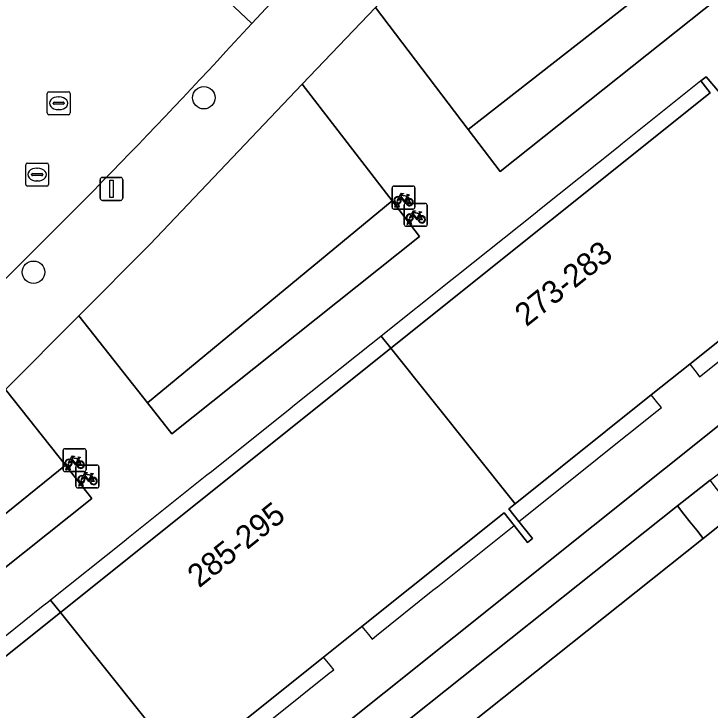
# Model space of a CAD drawing. Extents: x 159039 to 160102, y 381214 to 382524.
# Drawn here: x 159523.2 to 159553.55, y 381664.14 to 381694.48 of the extents above; entities that cross this region are included whole.
import ezdxf

# ---------------------------------------------------------------- set-up
doc = ezdxf.new("R2010")
doc.units = 0
for name, color, linetype in [('IMGEO_Boom', 7, 'Continuous'), ('IMGEO_Erf', 7, 'Continuous'), ('IMGEO_Fietsenrek', 7, 'Continuous'), ('IMGEO_Groenvoorziening', 7, 'Continuous'), ('IMGEO_Haag', 7, 'Continuous'), ('IMGEO_Lichtmast', 7, 'Continuous'), ('IMGEO_Pand', 7, 'Continuous'), ('IMGEO_Pand_nummerreeks', 7, 'Continuous'), ('IMGEO_Pand_overbouw', 7, 'Continuous'), ('IMGEO_Parkeervlak_open', 7, 'Continuous'), ('IMGEO_Rijbaan_lokaal_open', 7, 'Continuous'), ('IMGEO_Rioolput', 7, 'Continuous'), ('IMGEO_Voetpad_gesloten', 7, 'Continuous'), ('IMGEO_Voetpad_open', 7, 'Continuous')]:
    doc.layers.add(name, color=color, linetype=linetype)

msp = doc.modelspace()

# ---------------------------------------------------------------- linework, layer by layer
at = {"layer": 'IMGEO_Boom'}
for centre in [(159531.476, 381690.832), (159524.052, 381683.223)]:
    msp.add_circle(centre, 0.489, dxfattribs=at)
at = {"layer": 'IMGEO_Erf'}
for points in [[(159558.941, 381684.231), (159552.662, 381679.211), (159550.989, 381677.874), (159545.05, 381673.126), (159544.771, 381672.902), (159545.21, 381672.353), (159545.804, 381671.609), (159545.597, 381671.439), (159545.004, 381672.187), (159544.572, 381672.732), (159538.373, 381667.778), (159536.701, 381666.442), (159530.643, 381661.602)], [(159517.986, 381647.841), (159560.674, 381681.936), (159563.337, 381681.842), (159568.876, 381676.789), (159590.803, 381656.219)]]:
    msp.add_lwpolyline(points, dxfattribs=at)
at = {"layer": 'IMGEO_Fietsenrek'}
for p, q in [((159539.758, 381686.977), (159540.599, 381686.977)), ((159540.599, 381686.977), (159539.758, 381686.977)), ((159539.683, 381686.052), (159539.683, 381686.893)), ((159539.683, 381686.893), (159539.683, 381686.052)), ((159540.683, 381686.902), (159540.683, 381686.061)), ((159540.683, 381686.061), (159540.683, 381686.902)), ((159540.37, 381686.526), (159540.406, 381686.431)), ((159539.81, 381686.061), (159539.849, 381686.221)), ((159539.844, 381686.061), (159539.81, 381686.061)), ((159539.879, 381686.209), (159539.844, 381686.061)), ((159539.921, 381686.233), (159539.92, 381686.237)), ((159539.962, 381686.061), (159539.928, 381686.203)), ((159539.952, 381686.244), (159539.953, 381686.237)), ((159539.96, 381686.207), (159539.995, 381686.061)), ((159539.995, 381686.061), (159539.962, 381686.061)), ((159540.214, 381685.299), (159540.214, 381686.14)), ((159540.214, 381686.14), (159540.214, 381685.299)), ((159540.289, 381686.224), (159541.13, 381686.224)), ((159541.13, 381686.224), (159540.289, 381686.224)), ((159541.214, 381686.149), (159541.214, 381685.308)), ((159541.214, 381685.308), (159541.214, 381686.149)), ((159540.608, 381685.977), (159539.767, 381685.977)), ((159539.767, 381685.977), (159540.608, 381685.977)), ((159540.901, 381685.773), (159540.937, 381685.678)), ((159540.341, 381685.308), (159540.38, 381685.468)), ((159540.41, 381685.456), (159540.375, 381685.308)), ((159540.452, 381685.48), (159540.451, 381685.484)), ((159540.493, 381685.308), (159540.459, 381685.45)), ((159540.483, 381685.491), (159540.484, 381685.484)), ((159540.491, 381685.454), (159540.526, 381685.308)), ((159541.139, 381685.224), (159540.298, 381685.224)), ((159540.298, 381685.224), (159541.139, 381685.224)), ((159540.375, 381685.308), (159540.341, 381685.308)), ((159540.526, 381685.308), (159540.493, 381685.308)), ((159525.34, 381674.605), (159525.34, 381675.446)), ((159525.34, 381675.446), (159525.34, 381674.605)), ((159525.415, 381675.53), (159526.256, 381675.53)), ((159526.256, 381675.53), (159525.415, 381675.53)), ((159526.34, 381675.455), (159526.34, 381674.614)), ((159526.34, 381674.614), (159526.34, 381675.455)), ((159526.027, 381675.079), (159526.063, 381674.984)), ((159525.467, 381674.614), (159525.506, 381674.774)), ((159525.578, 381674.786), (159525.577, 381674.79)), ((159525.609, 381674.797), (159525.61, 381674.79)), ((159525.977, 381674.818), (159526.818, 381674.818)), ((159526.818, 381674.818), (159525.977, 381674.818)), ((159526.265, 381674.53), (159525.424, 381674.53)), ((159525.424, 381674.53), (159526.265, 381674.53)), ((159525.501, 381674.614), (159525.467, 381674.614)), ((159525.536, 381674.762), (159525.501, 381674.614)), ((159525.619, 381674.614), (159525.585, 381674.756)), ((159525.617, 381674.76), (159525.652, 381674.614)), ((159525.652, 381674.614), (159525.619, 381674.614)), ((159525.902, 381673.893), (159525.902, 381674.734)), ((159525.902, 381674.734), (159525.902, 381673.893)), ((159526.902, 381674.743), (159526.902, 381673.902)), ((159526.902, 381673.902), (159526.902, 381674.743)), ((159526.589, 381674.367), (159526.625, 381674.272)), ((159526.029, 381673.902), (159526.068, 381674.062)), ((159526.063, 381673.902), (159526.029, 381673.902)), ((159526.098, 381674.05), (159526.063, 381673.902)), ((159526.14, 381674.074), (159526.139, 381674.078)), ((159526.181, 381673.902), (159526.147, 381674.044)), ((159526.171, 381674.085), (159526.172, 381674.078)), ((159526.179, 381674.048), (159526.214, 381673.902)), ((159526.214, 381673.902), (159526.181, 381673.902)), ((159526.827, 381673.818), (159525.986, 381673.818)), ((159525.986, 381673.818), (159526.827, 381673.818))]:
    msp.add_line(p, q, dxfattribs=at)
for points in [[(159539.996, 381686.503), (159540.091, 381686.667), (159540.177, 381686.653), (159540.179, 381686.644), (159540.123, 381686.633), (159540.096, 381686.588), (159540.352, 381686.547)], [(159540.352, 381686.547), (159540.377, 381686.596), (159540.371, 381686.6), (159540.348, 381686.604), (159540.336, 381686.611), (159540.335, 381686.614), (159540.337, 381686.619), (159540.432, 381686.604), (159540.434, 381686.594), (159540.424, 381686.581), (159540.412, 381686.575), (159540.398, 381686.581), (159540.37, 381686.526)], [(159540.017, 381686.451), (159539.965, 381686.361), (159539.925, 381686.336), (159539.926, 381686.383), (159539.981, 381686.477)], [(159540.292, 381686.259), (159540.242, 381686.259), (159540.051, 381686.51), (159540.032, 381686.478)], [(159540.339, 381686.522), (159540.082, 381686.563), (159540.065, 381686.534), (159540.232, 381686.314), (159540.339, 381686.522)], [(159540.387, 381686.424), (159540.357, 381686.501), (159540.248, 381686.283), (159540.291, 381686.283)], [(159540.321, 381686.283), (159540.441, 381686.282), (159540.397, 381686.396)], [(159540.417, 381686.403), (159540.472, 381686.258), (159540.322, 381686.258)], [(159540.548, 381685.698), (159540.496, 381685.608), (159540.456, 381685.583), (159540.457, 381685.63), (159540.512, 381685.724)], [(159540.527, 381685.75), (159540.622, 381685.914), (159540.708, 381685.9), (159540.71, 381685.891), (159540.654, 381685.88), (159540.627, 381685.835), (159540.883, 381685.794)], [(159540.823, 381685.506), (159540.773, 381685.506), (159540.582, 381685.757), (159540.563, 381685.725)], [(159540.87, 381685.769), (159540.613, 381685.81), (159540.596, 381685.781), (159540.763, 381685.561), (159540.87, 381685.769)], [(159540.918, 381685.671), (159540.888, 381685.748), (159540.779, 381685.53), (159540.822, 381685.53)], [(159540.883, 381685.794), (159540.908, 381685.843), (159540.902, 381685.847), (159540.879, 381685.851), (159540.867, 381685.858), (159540.866, 381685.861), (159540.868, 381685.866), (159540.963, 381685.851), (159540.965, 381685.841), (159540.955, 381685.828), (159540.943, 381685.822), (159540.929, 381685.828), (159540.901, 381685.773)], [(159540.852, 381685.53), (159540.972, 381685.529), (159540.928, 381685.643)], [(159540.948, 381685.65), (159541.003, 381685.505), (159540.853, 381685.505)], [(159525.653, 381675.056), (159525.748, 381675.22), (159525.834, 381675.206), (159525.836, 381675.197), (159525.78, 381675.186), (159525.753, 381675.141), (159526.009, 381675.1)], [(159525.996, 381675.075), (159525.739, 381675.116), (159525.722, 381675.087), (159525.889, 381674.867), (159525.996, 381675.075)], [(159526.009, 381675.1), (159526.034, 381675.149), (159526.028, 381675.153), (159526.005, 381675.157), (159525.993, 381675.164), (159525.992, 381675.167), (159525.994, 381675.172), (159526.089, 381675.157), (159526.091, 381675.147), (159526.081, 381675.134), (159526.069, 381675.128), (159526.055, 381675.134), (159526.027, 381675.079)], [(159525.674, 381675.004), (159525.622, 381674.914), (159525.582, 381674.889), (159525.583, 381674.936), (159525.638, 381675.03)], [(159525.949, 381674.812), (159525.899, 381674.812), (159525.708, 381675.063), (159525.689, 381675.031)], [(159526.044, 381674.977), (159526.014, 381675.054), (159525.905, 381674.836), (159525.948, 381674.836)], [(159525.978, 381674.836), (159526.098, 381674.835), (159526.054, 381674.949)], [(159526.074, 381674.956), (159526.129, 381674.811), (159525.979, 381674.811)], [(159526.215, 381674.344), (159526.31, 381674.508), (159526.396, 381674.494), (159526.398, 381674.485), (159526.342, 381674.474), (159526.315, 381674.429), (159526.571, 381674.388)], [(159526.236, 381674.292), (159526.184, 381674.202), (159526.144, 381674.177), (159526.145, 381674.224), (159526.2, 381674.318)], [(159526.511, 381674.1), (159526.461, 381674.1), (159526.27, 381674.351), (159526.251, 381674.319)], [(159526.558, 381674.363), (159526.301, 381674.404), (159526.284, 381674.375), (159526.451, 381674.155), (159526.558, 381674.363)], [(159526.606, 381674.265), (159526.576, 381674.342), (159526.467, 381674.124), (159526.51, 381674.124)], [(159526.54, 381674.124), (159526.66, 381674.123), (159526.616, 381674.237)], [(159526.636, 381674.244), (159526.691, 381674.099), (159526.541, 381674.099)], [(159526.571, 381674.388), (159526.596, 381674.437), (159526.59, 381674.441), (159526.567, 381674.445), (159526.555, 381674.452), (159526.554, 381674.455), (159526.556, 381674.46), (159526.651, 381674.445), (159526.653, 381674.435), (159526.643, 381674.422), (159526.631, 381674.416), (159526.617, 381674.422), (159526.589, 381674.367)]]:
    msp.add_lwpolyline(points, dxfattribs=at)
for centre, radius, start, end in [((159539.761, 381686.899), 0.0779, 92.4484, 184.2845), ((159539.761, 381686.899), 0.0779, 92.4484, 184.2845), ((159540.605, 381686.899), 0.0779, 2.4484, 94.2845), ((159540.605, 381686.899), 0.0779, 2.4484, 94.2845), ((159539.923, 381686.362), 0.159, 62.6766, 242.1369), ((159539.923, 381686.362), 0.129, 63.3192, 238.903), ((159539.923, 381686.362), 0.129, 283.6043, 43.4302), ((159539.923, 381686.362), 0.159, 283.5766, 46.6042), ((159540.45, 381686.278), 0.159, 113.3408, 178.3217), ((159540.45, 381686.278), 0.159, 187.0065, 105.7708), ((159540.45, 381686.278), 0.129, 113.923, 177.9556), ((159540.45, 381686.278), 0.129, 188.6715, 104.5883), ((159539.761, 381686.055), 0.0779, 182.4484, 274.2845), ((159539.761, 381686.055), 0.0779, 182.4484, 274.2845), ((159539.903, 381686.233), 0.0499, 12.8025, 158.6934), ((159539.923, 381686.362), 0.159, 253.9967, 271.7867), ((159539.903, 381686.233), 0.0174, 12.8025, 163.4502), ((159539.923, 381686.362), 0.129, 253.415, 269.0204), ((159540.292, 381686.146), 0.0779, 92.4484, 184.2845), ((159540.292, 381686.146), 0.0779, 92.4484, 184.2845), ((159540.605, 381686.055), 0.0779, 272.4484, 4.2845), ((159540.605, 381686.055), 0.0779, 272.4484, 4.2845), ((159541.136, 381686.146), 0.0779, 2.4484, 94.2845), ((159541.136, 381686.146), 0.0779, 2.4484, 94.2845), ((159540.454, 381685.609), 0.159, 62.6766, 242.1369), ((159540.454, 381685.609), 0.129, 63.3192, 238.903), ((159540.454, 381685.609), 0.129, 283.6043, 43.4302), ((159540.454, 381685.609), 0.159, 283.5766, 46.6042), ((159540.434, 381685.48), 0.0499, 12.8025, 158.6934), ((159540.454, 381685.609), 0.159, 253.9967, 271.7867), ((159540.434, 381685.48), 0.0174, 12.8025, 163.4502), ((159540.454, 381685.609), 0.129, 253.415, 269.0204), ((159540.981, 381685.525), 0.159, 113.3408, 178.3217), ((159540.981, 381685.525), 0.159, 187.0065, 105.7708), ((159540.981, 381685.525), 0.129, 113.923, 177.9556), ((159540.981, 381685.525), 0.129, 188.6715, 104.5883), ((159540.292, 381685.302), 0.0779, 182.4484, 274.2845), ((159540.292, 381685.302), 0.0779, 182.4484, 274.2845), ((159541.136, 381685.302), 0.0779, 272.4484, 4.2845), ((159541.136, 381685.302), 0.0779, 272.4484, 4.2845), ((159525.418, 381675.452), 0.0779, 92.4484, 184.2845), ((159525.418, 381675.452), 0.0779, 92.4484, 184.2845), ((159526.262, 381675.452), 0.0779, 2.4484, 94.2845), ((159526.262, 381675.452), 0.0779, 2.4484, 94.2845), ((159525.58, 381674.915), 0.159, 62.6766, 242.1369), ((159525.58, 381674.915), 0.129, 63.3192, 238.903), ((159525.56, 381674.786), 0.0499, 12.8025, 158.6934), ((159525.56, 381674.786), 0.0174, 12.8025, 163.4502), ((159525.58, 381674.915), 0.129, 253.415, 269.0204), ((159525.58, 381674.915), 0.129, 283.6043, 43.4302), ((159525.58, 381674.915), 0.159, 283.5766, 46.6042), ((159525.98, 381674.74), 0.0779, 92.4484, 184.2845), ((159525.98, 381674.74), 0.0779, 92.4484, 184.2845), ((159526.107, 381674.831), 0.159, 113.3408, 178.3217), ((159526.107, 381674.831), 0.159, 187.0065, 105.7708), ((159526.107, 381674.831), 0.129, 113.923, 177.9556), ((159526.107, 381674.831), 0.129, 188.6715, 104.5883), ((159526.824, 381674.74), 0.0779, 2.4484, 94.2845), ((159526.824, 381674.74), 0.0779, 2.4484, 94.2845), ((159525.418, 381674.608), 0.0779, 182.4484, 274.2845), ((159525.418, 381674.608), 0.0779, 182.4484, 274.2845), ((159525.58, 381674.915), 0.159, 253.9967, 271.7867), ((159526.262, 381674.608), 0.0779, 272.4484, 4.2845), ((159526.262, 381674.608), 0.0779, 272.4484, 4.2845), ((159526.142, 381674.203), 0.159, 62.6766, 242.1369), ((159526.142, 381674.203), 0.129, 63.3192, 238.903), ((159526.142, 381674.203), 0.129, 283.6043, 43.4302), ((159526.142, 381674.203), 0.159, 283.5766, 46.6042), ((159526.669, 381674.119), 0.159, 113.3408, 178.3217), ((159526.669, 381674.119), 0.159, 187.0065, 105.7708), ((159526.669, 381674.119), 0.129, 113.923, 177.9556), ((159526.669, 381674.119), 0.129, 188.6715, 104.5883), ((159525.98, 381673.896), 0.0779, 182.4484, 274.2845), ((159525.98, 381673.896), 0.0779, 182.4484, 274.2845), ((159526.122, 381674.074), 0.0499, 12.8025, 158.6934), ((159526.142, 381674.203), 0.159, 253.9967, 271.7867), ((159526.122, 381674.074), 0.0174, 12.8025, 163.4502), ((159526.142, 381674.203), 0.129, 253.415, 269.0204), ((159526.824, 381673.896), 0.0779, 272.4484, 4.2845), ((159526.824, 381673.896), 0.0779, 272.4484, 4.2845)]:
    msp.add_arc(centre, radius, start, end, dxfattribs=at)
at = {"layer": 'IMGEO_Groenvoorziening'}
for points in [[(159552.118, 381708.936), (159538.96, 381694.765), (159543.002, 381689.45), (159559.385, 381702.243)], [(159544.393, 381687.62), (159560.959, 381700.793), (159559.385, 381702.243), (159543.002, 381689.45)], [(159526.033, 381681.326), (159529.018, 381677.537), (159539.688, 381686.33), (159535.768, 381691.423), (159529.122, 381684.438)], [(159530.088, 381676.179), (159540.878, 381684.784), (159539.688, 381686.33), (159529.018, 381677.537)], [(159512.874, 381668.486), (159514.696, 381666.122), (159525.44, 381674.816), (159522.833, 381678.114)], [(159515.763, 381664.736), (159526.592, 381673.359), (159525.44, 381674.816), (159514.696, 381666.122)], [(159553.246, 381671.62), (159552.968, 381671.974), (159552.69, 381672.328), (159552.412, 381672.682), (159552.129, 381673.041), (159539.094, 381662.668), (159539.379, 381662.302), (159539.656, 381661.947), (159539.933, 381661.592), (159540.21, 381661.238)]]:
    msp.add_lwpolyline(points, close=True, dxfattribs=at)
msp.add_lwpolyline([(159559.955, 381676.816), (159554.67, 381672.743), (159553.246, 381671.62), (159540.21, 381661.238), (159538.785, 381660.093), (159526.133, 381649.947), (159524.729, 381648.803), (159520.146, 381645.173), (159518.283, 381643.698), (159520.549, 381641.574)], dxfattribs=at)
at = {"layer": 'IMGEO_Haag'}
for points in [[(159530.088, 381676.179), (159540.878, 381684.784), (159539.688, 381686.33), (159529.018, 381677.537)], [(159515.763, 381664.736), (159526.592, 381673.359), (159525.44, 381674.816), (159514.696, 381666.122)], [(159553.246, 381671.62), (159552.968, 381671.974), (159552.69, 381672.328), (159552.412, 381672.682), (159552.129, 381673.041), (159539.094, 381662.668), (159539.379, 381662.302), (159539.656, 381661.947), (159539.933, 381661.592), (159540.21, 381661.238)]]:
    msp.add_lwpolyline(points, close=True, dxfattribs=at)
at = {"layer": 'IMGEO_Lichtmast'}
for p, q in [((159526.953, 381686.457), (159526.953, 381687.257)), ((159526.953, 381687.257), (159526.953, 381686.457)), ((159527.053, 381687.357), (159527.843, 381687.357)), ((159527.843, 381687.357), (159527.053, 381687.357)), ((159527.943, 381687.257), (159527.943, 381686.457)), ((159527.943, 381686.457), (159527.943, 381687.257)), ((159527.843, 381686.357), (159527.053, 381686.357)), ((159527.053, 381686.357), (159527.843, 381686.357))]:
    msp.add_line(p, q, dxfattribs=at)
msp.add_lwpolyline([(159527.373, 381687.232), (159527.523, 381687.232), (159527.523, 381686.482), (159527.373, 381686.482), (159527.373, 381687.232)], dxfattribs=at)
for centre, start, end in [((159527.053, 381687.257), 90, 180), ((159527.053, 381687.257), 90, 180), ((159527.843, 381687.257), 0, 90), ((159527.843, 381687.257), 360, 90), ((159527.053, 381686.457), 180, 270), ((159527.053, 381686.457), 180, 270), ((159527.843, 381686.457), 270, 0), ((159527.843, 381686.457), 270, 0)]:
    msp.add_arc(centre, 0.1, start, end, dxfattribs=at)
at = {"layer": 'IMGEO_Pand'}
for points in [[(159560.022, 381684.192), (159554.358, 381690.875), (159554.21, 381690.76), (159553.382, 381691.743), (159553.148, 381691.563), (159553.55, 381691.042), (159539.633, 381679.917), (159545.05, 381673.126), (159550.989, 381677.874), (159552.662, 381679.211), (159558.941, 381684.231), (159559.37, 381683.693), (159559.846, 381683.094), (159559.969, 381683.194), (159560.081, 381683.281), (159559.612, 381683.878)], [(159525.223, 381668.397), (159530.643, 381661.602), (159536.701, 381666.442), (159538.373, 381667.778), (159544.572, 381672.732), (159545.004, 381672.187), (159545.597, 381671.439), (159545.804, 381671.609), (159545.21, 381672.353), (159544.771, 381672.902), (159545.05, 381673.126), (159539.633, 381679.917)], [(159525.223, 381668.397), (159510.714, 381656.799), (159510.259, 381657.341), (159510.034, 381657.157), (159516.34, 381649.275), (159516.469, 381649.378), (159516.574, 381649.462), (159516.137, 381650.009), (159522.394, 381655.014), (159524.075, 381656.36), (159530.263, 381661.309), (159530.703, 381660.756), (159531.304, 381660.003), (159531.511, 381660.175), (159530.909, 381660.92), (159530.47, 381661.464), (159530.643, 381661.602)]]:
    msp.add_lwpolyline(points, close=True, dxfattribs=at)
at = {"layer": 'IMGEO_Pand_overbouw'}
for points in [[(159553.148, 381691.563), (159549.727, 381688.831), (159549.539, 381688.681), (159546.112, 381685.945), (159545.918, 381685.79), (159542.502, 381683.063), (159542.305, 381682.906), (159539.216, 381680.44), (159539.633, 381679.917), (159553.55, 381691.042)], [(159559.37, 381683.693), (159558.941, 381684.231), (159552.662, 381679.211), (159552.939, 381678.865), (159553.095, 381678.67), (159553.292, 381678.828), (159555.778, 381680.818), (159555.98, 381680.979)], [(159539.633, 381679.917), (159539.216, 381680.44), (159538.972, 381680.245), (159538.774, 381680.088), (159535.436, 381677.422), (159535.246, 381677.271), (159531.809, 381674.527), (159531.614, 381674.372), (159528.2, 381671.646), (159528.001, 381671.487), (159524.798, 381668.93), (159525.223, 381668.397)], [(159545.05, 381673.126), (159544.771, 381672.902), (159545.21, 381672.353), (159548.537, 381675.014), (159548.717, 381675.158), (159551.234, 381677.172), (159551.427, 381677.326), (159551.271, 381677.521), (159550.989, 381677.874)], [(159538.373, 381667.778), (159538.654, 381667.427), (159538.81, 381667.232), (159539.004, 381667.387), (159541.469, 381669.359), (159541.665, 381669.516), (159545.004, 381672.187), (159544.572, 381672.732)], [(159525.223, 381668.397), (159524.798, 381668.93), (159524.677, 381668.833), (159524.478, 381668.675), (159521.138, 381666.008), (159520.939, 381665.849), (159517.513, 381663.114), (159517.312, 381662.954), (159513.901, 381660.23), (159513.697, 381660.068), (159510.259, 381657.341), (159510.714, 381656.799)], [(159530.643, 381661.602), (159530.47, 381661.464), (159530.909, 381660.92), (159534.256, 381663.592), (159534.448, 381663.745), (159536.948, 381665.741), (159537.139, 381665.894), (159536.983, 381666.089), (159536.701, 381666.442)]]:
    msp.add_lwpolyline(points, close=True, dxfattribs=at)
at = {"layer": 'IMGEO_Parkeervlak_open'}
msp.add_lwpolyline([(159546.267, 381710.129), (159544.91, 381708.807), (159532.297, 381695.293), (159533.57, 381694.071), (159545.425, 381706.782)], dxfattribs=at)
at = {"layer": 'IMGEO_Rijbaan_lokaal_open'}
msp.add_lwpolyline([(159533.57, 381694.071), (159532.297, 381695.293), (159529.21, 381698.27), (159528.664, 381697.665), (159527.907, 381696.872)], dxfattribs=at)
msp.add_arc((159323.736, 381885.879), 284.29, 313.99126, 317.56976, dxfattribs=at)
at = {"layer": 'IMGEO_Rioolput'}
for p, q in [((159524.65, 381690.165), (159524.65, 381691.017)), ((159524.725, 381691.091), (159525.577, 381691.091)), ((159525.138, 381690.871), (159525.163, 381690.871)), ((159525.651, 381691.017), (159525.651, 381690.165)), ((159524.909, 381690.585), (159524.909, 381690.597)), ((159524.952, 381690.634), (159525.35, 381690.634)), ((159525.393, 381690.597), (159525.393, 381690.585)), ((159525.347, 381690.548), (159524.949, 381690.548)), ((159525.161, 381690.311), (159525.136, 381690.311)), ((159525.577, 381690.091), (159524.725, 381690.091)), ((159523.71, 381687.054), (159523.71, 381687.906)), ((159523.785, 381687.98), (159524.637, 381687.98)), ((159524.711, 381687.906), (159524.711, 381687.054)), ((159524.012, 381687.523), (159524.41, 381687.523)), ((159524.198, 381687.76), (159524.223, 381687.76)), ((159523.969, 381687.474), (159523.969, 381687.486)), ((159524.407, 381687.437), (159524.009, 381687.437)), ((159524.453, 381687.486), (159524.453, 381687.474)), ((159524.637, 381686.98), (159523.785, 381686.98)), ((159524.221, 381687.2), (159524.196, 381687.2))]:
    msp.add_line(p, q, dxfattribs=at)
for points in [[(159524.65, 381690.165), (159524.65, 381691.017)], [(159524.725, 381691.091), (159525.577, 381691.091)], [(159525.651, 381691.017), (159525.651, 381690.165)], [(159525.577, 381690.091), (159524.725, 381690.091)], [(159523.71, 381687.054), (159523.71, 381687.906)], [(159523.785, 381687.98), (159524.637, 381687.98)], [(159524.711, 381687.906), (159524.711, 381687.054)], [(159524.637, 381686.98), (159523.785, 381686.98)]]:
    msp.add_lwpolyline(points, dxfattribs=at)
for centre, radius, start, end in [((159524.727, 381691.015), 0.0765, 91.552, 178.448), ((159524.727, 381691.015), 0.0765, 91.552, 178.448), ((159525.575, 381691.015), 0.0765, 1.552, 88.448), ((159525.575, 381691.015), 0.0765, 1.552, 88.448), ((159524.949, 381690.594), 0.0403, 85.8775, 175.7526), ((159524.946, 381690.584), 0.0366, 178.938, 274.7102), ((159525.35, 381690.591), 0.043, 264.8664, 352.4533), ((159525.354, 381690.596), 0.0386, 1.7309, 96.639), ((159524.727, 381690.167), 0.0765, 181.552, 268.448), ((159524.727, 381690.167), 0.0765, 181.552, 268.448), ((159525.575, 381690.167), 0.0765, 271.552, 358.448), ((159525.575, 381690.167), 0.0765, 271.552, 358.448), ((159523.787, 381687.904), 0.0765, 91.552, 178.448), ((159523.787, 381687.904), 0.0765, 91.552, 178.448), ((159524.635, 381687.904), 0.0765, 1.552, 88.448), ((159524.635, 381687.904), 0.0765, 1.552, 88.448), ((159524.009, 381687.483), 0.0403, 85.8775, 175.7526), ((159524.414, 381687.485), 0.0386, 1.7309, 96.639), ((159524.006, 381687.473), 0.0366, 178.938, 274.7102), ((159524.41, 381687.48), 0.043, 264.8664, 352.4533), ((159523.787, 381687.056), 0.0765, 181.552, 268.448), ((159523.787, 381687.056), 0.0765, 181.552, 268.448), ((159524.635, 381687.056), 0.0765, 271.552, 358.448), ((159524.635, 381687.056), 0.0765, 271.552, 358.448)]:
    msp.add_arc(centre, radius, start, end, dxfattribs=at)
for centre, major_axis, ratio, start_param, end_param in [((159525.137, 381690.591), (-0.387, 0.002), 0.722429, 4.712389, 7.853982), ((159525.162, 381690.591), (-0.39, 0.002), 0.717154, 1.570796, 4.712389), ((159524.197, 381687.48), (-0.387, 0.002), 0.722429, 4.712389, 7.853982), ((159524.222, 381687.48), (-0.39, 0.002), 0.717154, 1.570796, 4.712389)]:
    msp.add_ellipse(centre, major_axis=major_axis, ratio=ratio, start_param=start_param, end_param=end_param, dxfattribs=at)
at = {"layer": 'IMGEO_Voetpad_gesloten'}
msp.add_lwpolyline([(159568.876, 381676.789), (159563.337, 381681.842), (159560.674, 381681.936), (159517.986, 381647.841), (159519.021, 381646.563), (159523.586, 381650.209), (159524.989, 381651.371), (159537.658, 381661.487), (159539.094, 381662.668), (159552.129, 381673.041), (159553.552, 381674.157), (159559.265, 381678.545)], dxfattribs=at)
at = {"layer": 'IMGEO_Voetpad_open'}
for points in [[(159529.122, 381684.438), (159535.768, 381691.423), (159538.96, 381694.765), (159552.118, 381708.936), (159554.341, 381711.429)], [(159545.425, 381706.782), (159533.57, 381694.071)], [(159560.959, 381700.793), (159544.393, 381687.62), (159543.002, 381689.45), (159538.96, 381694.765), (159535.768, 381691.423), (159539.688, 381686.33), (159540.878, 381684.784), (159530.088, 381676.179), (159529.018, 381677.537), (159526.033, 381681.326), (159522.833, 381678.114), (159525.44, 381674.816), (159526.592, 381673.359), (159515.763, 381664.736)], [(159539.633, 381679.917), (159553.55, 381691.042), (159553.148, 381691.563), (159553.382, 381691.743), (159554.21, 381690.76), (159554.358, 381690.875), (159559.36, 381694.754), (159560.018, 381693.83), (159561.29, 381693.768), (159561.367, 381695.083)], [(159503.53, 381657.53), (159506.037, 381658.997), (159504.688, 381660.71), (159509.598, 381665.306), (159512.874, 381668.486), (159522.833, 381678.114), (159526.033, 381681.326), (159529.122, 381684.438)], [(159510.714, 381656.799), (159525.223, 381668.397), (159539.633, 381679.917)]]:
    msp.add_lwpolyline(points, dxfattribs=at)
msp.add_lwpolyline([(159552.129, 381673.041), (159552.412, 381672.682), (159552.69, 381672.328), (159552.968, 381671.974), (159553.246, 381671.62), (159554.67, 381672.743), (159554.391, 381673.096), (159554.112, 381673.449), (159553.833, 381673.802), (159553.552, 381674.157)], close=True, dxfattribs=at)
msp.add_arc((159323.736, 381885.879), 284.29, 313.99126, 317.56976, dxfattribs=at)

# ---------------------------------------------------------------- texts
at = {"layer": 'IMGEO_Pand_nummerreeks'}
for s, p in [('273-283', (159545.544, 381680.821)), ('285-295', (159531.271, 381669.435))]:
    msp.add_text(s, height=1, rotation=38.5791, dxfattribs=at).set_placement(p)

doc.saveas('drawing.dxf')
